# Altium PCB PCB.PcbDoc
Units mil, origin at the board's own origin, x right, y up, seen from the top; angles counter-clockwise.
Board outline 6000 x 4000 mil, 2 copper layers (Top Layer, Bottom Layer); 8 components, 5 nets, 22 pads, 0 vias.
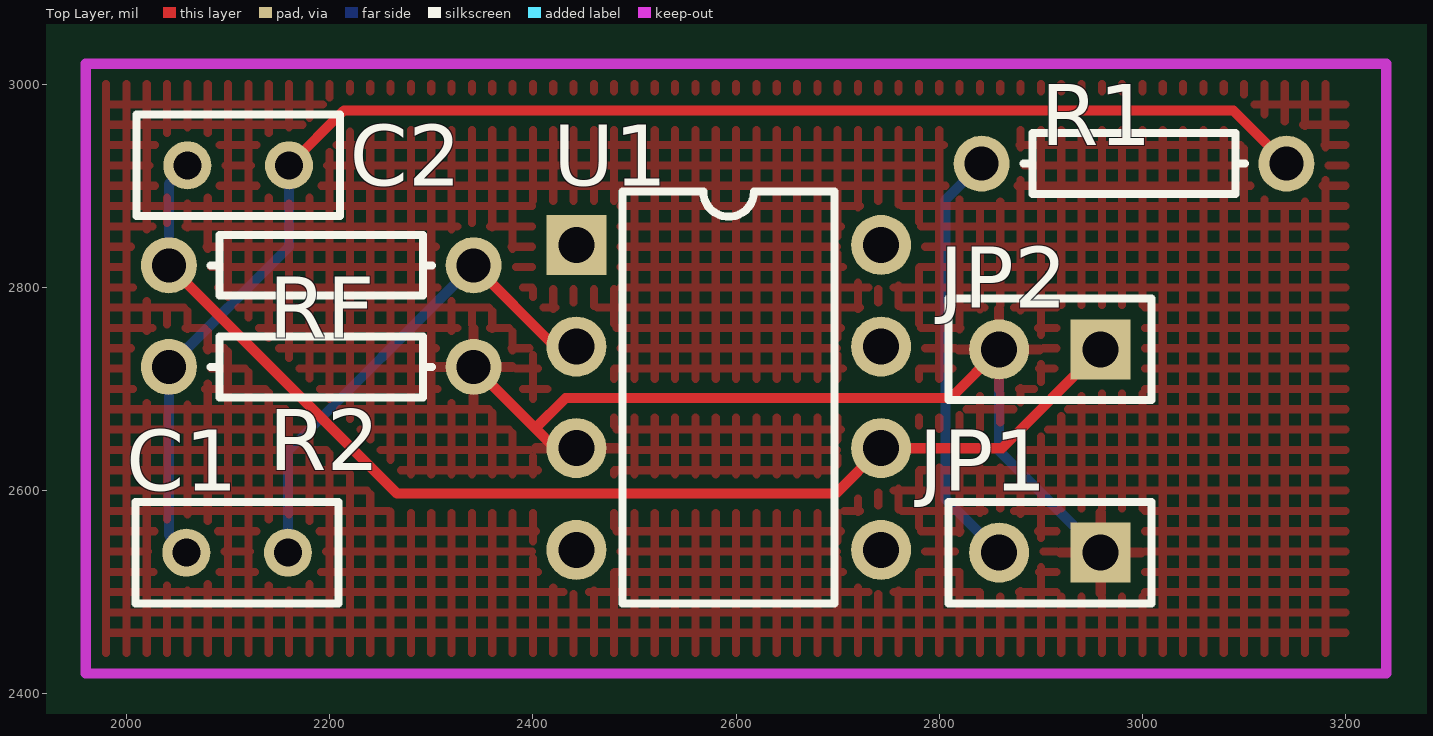
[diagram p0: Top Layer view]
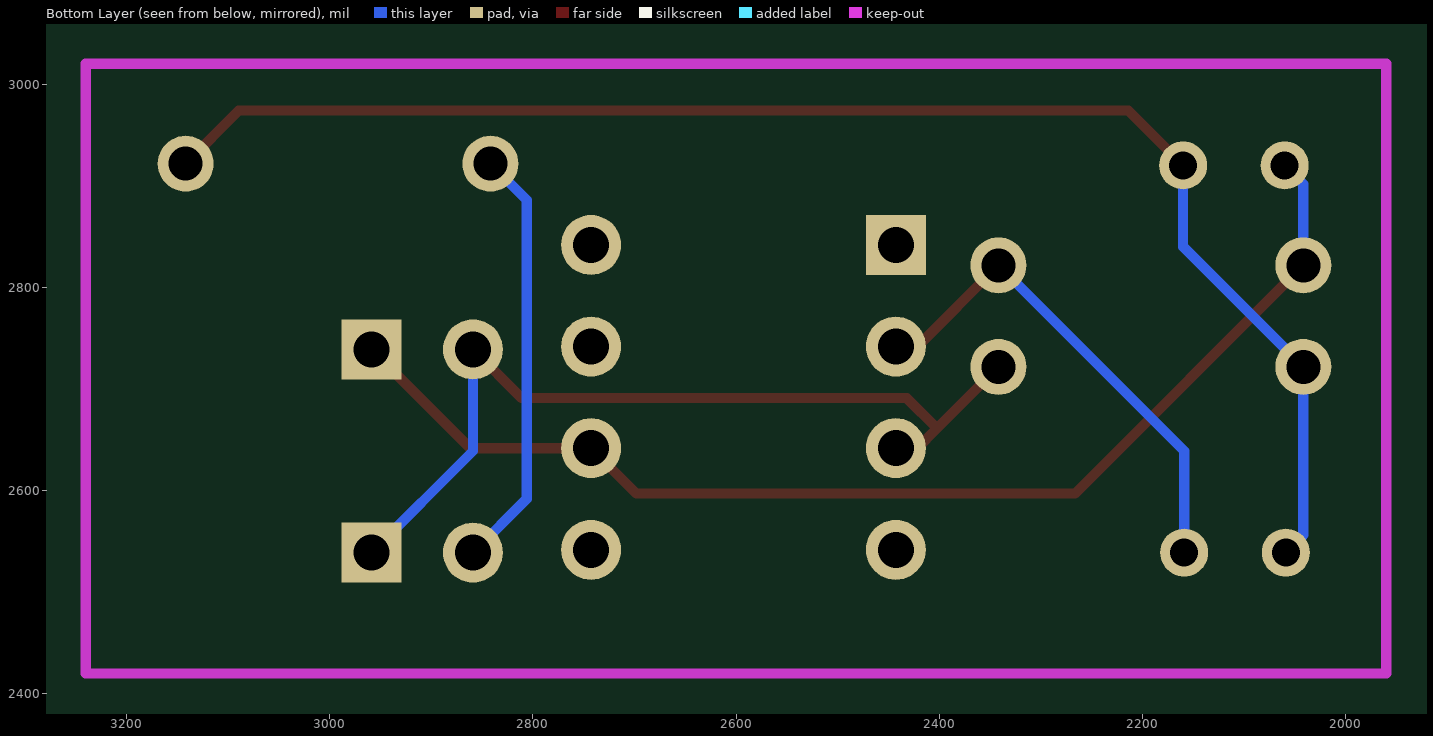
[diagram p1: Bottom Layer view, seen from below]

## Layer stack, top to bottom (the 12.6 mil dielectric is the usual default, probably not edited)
Top Layer: signal copper 1.4
Dielectric: dielectric 12.6, FR-4, Dk 4.8
Bottom Layer: signal copper 1.4

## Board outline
1000,1000 7000,1000 7000,5000 1000,5000

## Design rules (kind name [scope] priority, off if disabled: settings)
Clearance [All] p1: gap=10
ComponentClearance [All] p1: gap=10 collisioncheckmode=0
PolygonConnect [All] p1: connectstyle=Relief reliefconductorwidth=10 reliefentries=4 polygonreliefangle="90 Angle"
RoomDefinition Bandpass [InComponentClass('Bandpass')] p1: confinementstyle=ConfineIn formatcopy=TRUE outline 2000,2460 3240,2460 3240,2980 2000,2980
RoutingLayers [All] p1: top layer=Horizontal bottom layer=Vertical
RoutingVias [All] p1: holewidth=28 width=50 viastyle="Through Hole" minholewidth=28 minwidth=50 maxholewidth=28 maxwidth=50
SolderMaskExpansion [All] p1: expansion=4
TestPointUsage [All] p1: valid=0 allowmultiple=FALSE
Testpoint [All] p1: side=15 testpointundercomponent=TRUE minsize=40 maxsize=100 preferedsize=60 minholesize=0 maxholesize=40 preferedholesize=32 testpointgrid=1 style=1023 order=1234567890
Width [All] p1: maxlimit=10 minlimit=10 preferedwidth=10
16 further rules are at their usual default settings.

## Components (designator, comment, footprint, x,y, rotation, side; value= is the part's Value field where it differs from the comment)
C1 "0.02μF" RAD-0.1 2058.94,2538.94 r0 top
C2 "0.02μF" RAD-0.1 2160,2920 r180 top
JP1 "Header 2" HDR1X2 2958.94,2538.94 r180 top
JP2 "Header 2" HDR1X2 2958.94,2738.94 r180 top
R1 "39.8k" AXIAL-0.3 2991.73,2921.73 r180 top
R2 "401.9" AXIAL-0.3 2191.73,2721.73 r0 top
RF "159k" AXIAL-0.3 2191.73,2821.73 r180 top
U1 "UA741" DIP-8 2592.72,2691.69 r270 top

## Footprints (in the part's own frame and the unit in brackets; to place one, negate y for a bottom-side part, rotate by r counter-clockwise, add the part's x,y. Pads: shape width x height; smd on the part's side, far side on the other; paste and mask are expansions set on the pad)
AXIAL-0.3 [mm]
  round 1.4 hole 0.85: 1(-3.81,0) 2(3.81,0)
  silkscreen extent -2.77,-0.76 2.77,0.76
DIP-8 [mm]
  rect 1.5x1.5 hole 0.9: 1(-3.81,-3.81)
  round 1.5 hole 0.9: 2(-1.27,-3.81) 3(1.27,-3.81) 4(3.81,-3.81) 5(3.81,3.81) 6(1.27,3.81) 7(-1.27,3.81) 8(-3.81,3.81)
  silkscreen extent -5.15,-2.65 5.15,2.65
HDR1X2 [mm]
  rect 1.5x1.5 hole 0.9: 1(0,0)
  round 1.5 hole 0.9: 2(2.54,0)
  silkscreen extent -1.27,-1.27 3.81,1.27
RAD-0.1 [mm]
  round 1.2 hole 0.7: 1(0,0) 2(2.54,0)
  silkscreen extent -1.27,-1.27 3.81,1.27

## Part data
C1 C2: library part CAP, "Capacitor"
JP1 JP2: "Header, 2-Pin"
R1 R2 RF: library part RES, "Resistor"
U1: "General-Purpose Operational Amplifier"

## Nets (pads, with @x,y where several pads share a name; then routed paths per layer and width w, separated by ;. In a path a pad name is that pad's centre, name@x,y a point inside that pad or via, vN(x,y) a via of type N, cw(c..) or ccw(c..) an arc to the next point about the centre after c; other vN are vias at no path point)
GND: JP1.1 JP2.2 R2.2 U1.3 | length 864.4
  Top Layer w10: R2.2 2402.25,2661.21 ; U1.3 2421.77,2641.69 2402.25,2661.21 ; JP2.2 2811,2691 2432.04,2691 2402.25,2661.21
  Bottom Layer w10: JP2.2 2858.94,2638.94 JP1.1
NetC1_1: C1.1 C2.1 R1.1 R2.1 | length 1462.9
  Top Layer w10: C2.1 2214,2974 3089.46,2974 R1.1
  Bottom Layer w10: C1.1 2041.73,2556.14 R2.1 2160,2840 C2.1
NetC1_2: C1.2 RF.1 U1.2 | length 492.6
  Top Layer w10: RF.1 2421.77,2741.69 U1.2
  Bottom Layer w10: C1.2 2158.94,2638.94 RF.1
NetC2_2: C2.2 JP2.1 RF.2 U1.6 | length 1174.9
  Top Layer w10: RF.2 2266.46,2597 2698.02,2597 U1.6 2861.69,2641.69 JP2.1
  Bottom Layer w10: RF.2 2041.73,2901.73 C2.2
NetJP1_2: JP1.2 R1.2 | length 419.5
  Bottom Layer w10: R1.2 2806,2886 2806,2591.88 JP1.2
pads on no net: U1.1 U1.4 U1.5 U1.7 U1.8

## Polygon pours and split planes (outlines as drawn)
GND on Top Layer (hatched 90Degree grid 20 track 8): 1980,2980 1980,2440 3200,2440 3200,3000 1980,3000

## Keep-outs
Keep-Out Layer:
  lines w10: 1960,2420 1960,3020 3080,3020 3240,3020 3240,2420 1960,2420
